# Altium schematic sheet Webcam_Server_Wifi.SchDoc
size A
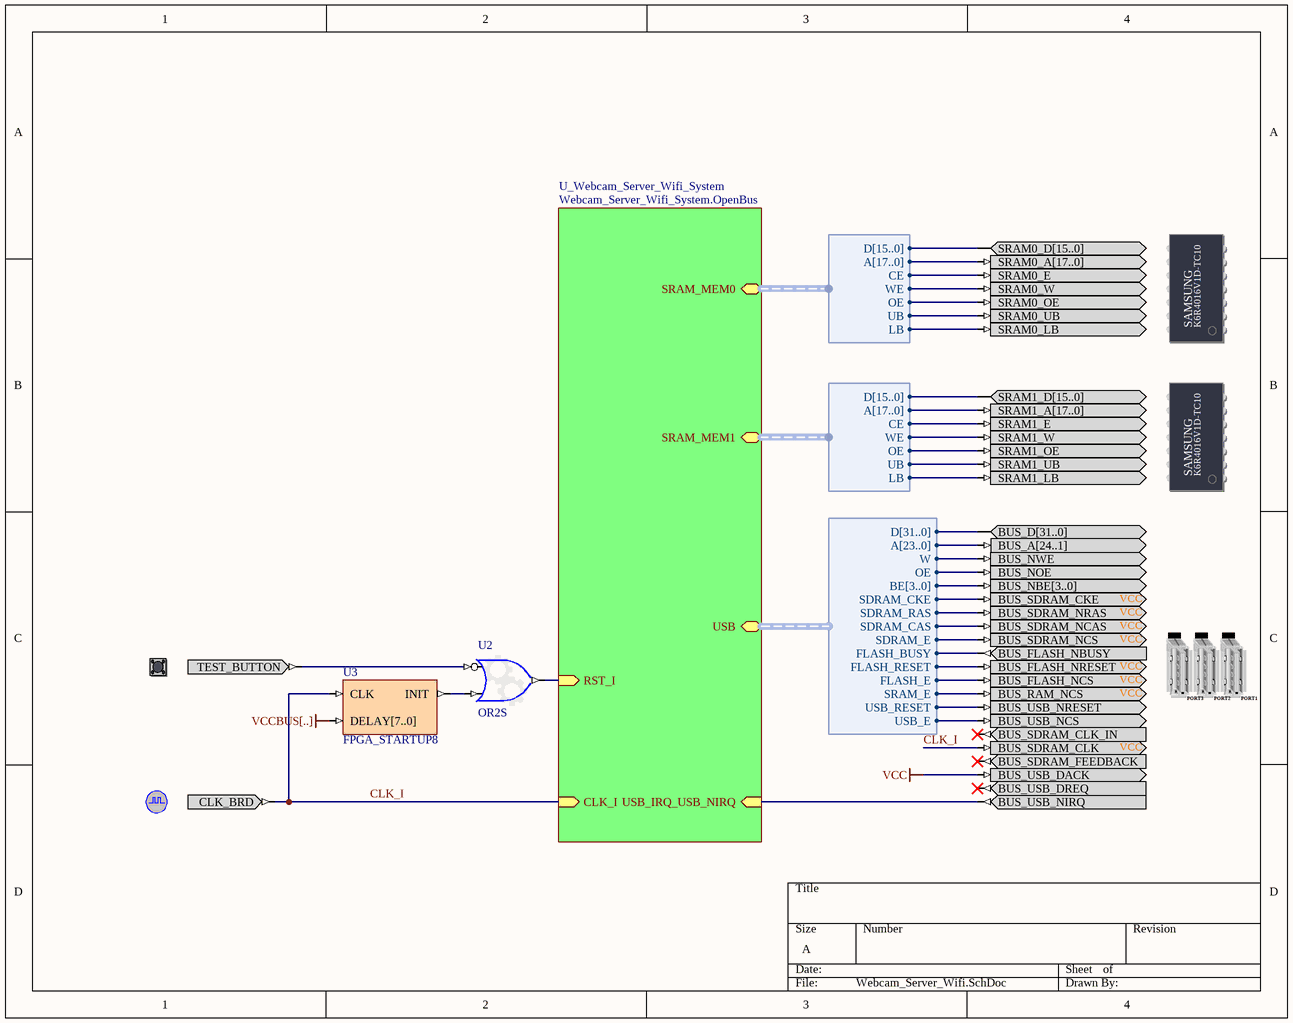
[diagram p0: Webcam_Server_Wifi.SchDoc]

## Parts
(Parts that share a designator on the sheet are numbered #1, #2 ... from top to bottom, then left to right.)
?#1  SRAM_DAUGHTER0  (value not drawn)
?#2  SRAM_DAUGHTER1  (value not drawn)
?#3  SHARED_USB  (value not drawn)
?#4  TEST_BUTTON  (value not drawn)
?#5  CLOCK_BOARD  (value not drawn)
U2  OR2S
U3  FPGA_STARTUP8

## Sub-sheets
U_Webcam_Server_Wifi_System = Webcam_Server_Wifi_System.OpenBus: SRAM_MEM0 (harness WB_MEM_CTRL_SRAM16_A18), SRAM_MEM1 (harness WB_MEM_CTRL_SRAM16_A18), RST_I (in), CLK_I (in), USB_IRQ_USB_NIRQ (in), USB (harness WB_SHARED_MEM_CTRL)

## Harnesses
WB_MEM_CTRL_SRAM16_A18: D[15..0], A[17..0], CE, WE, OE, UB, LB
WB_SHARED_MEM_CTRL: D[31..0], A[23..0], W, OE, BE[3..0], SDRAM_CKE, SDRAM_RAS, SDRAM_CAS, SDRAM_E, FLASH_BUSY, FLASH_RESET, FLASH_E, SRAM_E, USB_RESET, USB_E

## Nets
VCC: ?#3.BUS_USB_DACK
VCCBUS[..]: U3.DELAY[7..0]
CLK_I: ?#3.BUS_SDRAM_CLK ?#5.CLK_BRD U3.CLK ; sheet U_Webcam_Server_Wifi_System/CLK_I
Net?#1_SRAM0_E: ?#1.SRAM0_E ; sheet U_Webcam_Server_Wifi_System/SRAM_MEM0.CE
Net?#1_SRAM0_LB: ?#1.SRAM0_LB ; sheet U_Webcam_Server_Wifi_System/SRAM_MEM0.LB
Net?#1_SRAM0_OE: ?#1.SRAM0_OE ; sheet U_Webcam_Server_Wifi_System/SRAM_MEM0.OE
Net?#1_SRAM0_UB: ?#1.SRAM0_UB ; sheet U_Webcam_Server_Wifi_System/SRAM_MEM0.UB
Net?#1_SRAM0_W: ?#1.SRAM0_W ; sheet U_Webcam_Server_Wifi_System/SRAM_MEM0.WE
Net?#2_SRAM1_E: ?#2.SRAM1_E ; sheet U_Webcam_Server_Wifi_System/SRAM_MEM1.CE
Net?#2_SRAM1_LB: ?#2.SRAM1_LB ; sheet U_Webcam_Server_Wifi_System/SRAM_MEM1.LB
Net?#2_SRAM1_OE: ?#2.SRAM1_OE ; sheet U_Webcam_Server_Wifi_System/SRAM_MEM1.OE
Net?#2_SRAM1_UB: ?#2.SRAM1_UB ; sheet U_Webcam_Server_Wifi_System/SRAM_MEM1.UB
Net?#2_SRAM1_W: ?#2.SRAM1_W ; sheet U_Webcam_Server_Wifi_System/SRAM_MEM1.WE
Net?#3_BUS_FLASH_NBUSY: ?#3.BUS_FLASH_NBUSY ; sheet U_Webcam_Server_Wifi_System/USB.FLASH_BUSY
Net?#3_BUS_FLASH_NCS: ?#3.BUS_FLASH_NCS ; sheet U_Webcam_Server_Wifi_System/USB.FLASH_E
Net?#3_BUS_FLASH_NRESET: ?#3.BUS_FLASH_NRESET ; sheet U_Webcam_Server_Wifi_System/USB.FLASH_RESET
Net?#3_BUS_NOE: ?#3.BUS_NOE ; sheet U_Webcam_Server_Wifi_System/USB.OE
Net?#3_BUS_NWE: ?#3.BUS_NWE ; sheet U_Webcam_Server_Wifi_System/USB.W
Net?#3_BUS_RAM_NCS: ?#3.BUS_RAM_NCS ; sheet U_Webcam_Server_Wifi_System/USB.SRAM_E
Net?#3_BUS_SDRAM_CKE: ?#3.BUS_SDRAM_CKE ; sheet U_Webcam_Server_Wifi_System/USB.SDRAM_CKE
Net?#3_BUS_SDRAM_NCAS: ?#3.BUS_SDRAM_NCAS ; sheet U_Webcam_Server_Wifi_System/USB.SDRAM_CAS
Net?#3_BUS_SDRAM_NCS: ?#3.BUS_SDRAM_NCS ; sheet U_Webcam_Server_Wifi_System/USB.SDRAM_E
Net?#3_BUS_SDRAM_NRAS: ?#3.BUS_SDRAM_NRAS ; sheet U_Webcam_Server_Wifi_System/USB.SDRAM_RAS
Net?#3_BUS_USB_NCS: ?#3.BUS_USB_NCS ; sheet U_Webcam_Server_Wifi_System/USB.USB_E
Net?#3_BUS_USB_NIRQ: ?#3.BUS_USB_NIRQ ; sheet U_Webcam_Server_Wifi_System/USB_IRQ_USB_NIRQ
Net?#3_BUS_USB_NRESET: ?#3.BUS_USB_NRESET ; sheet U_Webcam_Server_Wifi_System/USB.USB_RESET
Net?#4_TEST_BUTTON: ?#4.TEST_BUTTON U2.I0
NetU2_I1: U2.I1 U3.INIT
NetU2_O: U2.O ; sheet U_Webcam_Server_Wifi_System/RST_I

Not connected (* = marked no-connect by the designer): ?#1 SRAM0_A[17..0] SRAM0_D[15..0]; ?#2 SRAM1_A[17..0] SRAM1_D[15..0]; ?#3 BUS_A[24..1] BUS_D[31..0] BUS_NBE[3..0] BUS_SDRAM_CLK_IN* BUS_SDRAM_FEEDBACK* BUS_USB_DREQ*

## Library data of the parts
?#1 = SRAM_DAUGHTER0: Free Static RAM - Daughterboard; PortComponent: True
?#2 = SRAM_DAUGHTER1: Free Static RAM - Daughterboard; PortComponent: True
?#3 = SHARED_USB: Common-Bus USB; PortComponent: True
?#4 = TEST_BUTTON: Test / Reset Button; PortComponent: True
?#5 = CLOCK_BOARD: Global System Clock Supply; PortComponent: True
U2 = GATE: Configurable Generic Gate; ConfiguratorName: GENERIC_GATE; ConfigurationParameters: {}Version[1.0]{}GateKind[OR]{}BusInput[False]{}GateInputType[Bit]{}GateOutputOption[Normal]{}BusWidth[8]{}RegisterOutputs[False]{}NegativeClockEdge[False]{}InputCount[2]{}InputInvert0[True]{}InputInvert1[False]{}
U3 = FPGA_STARTUP8: FPGA Startup With 8 Bit Delay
